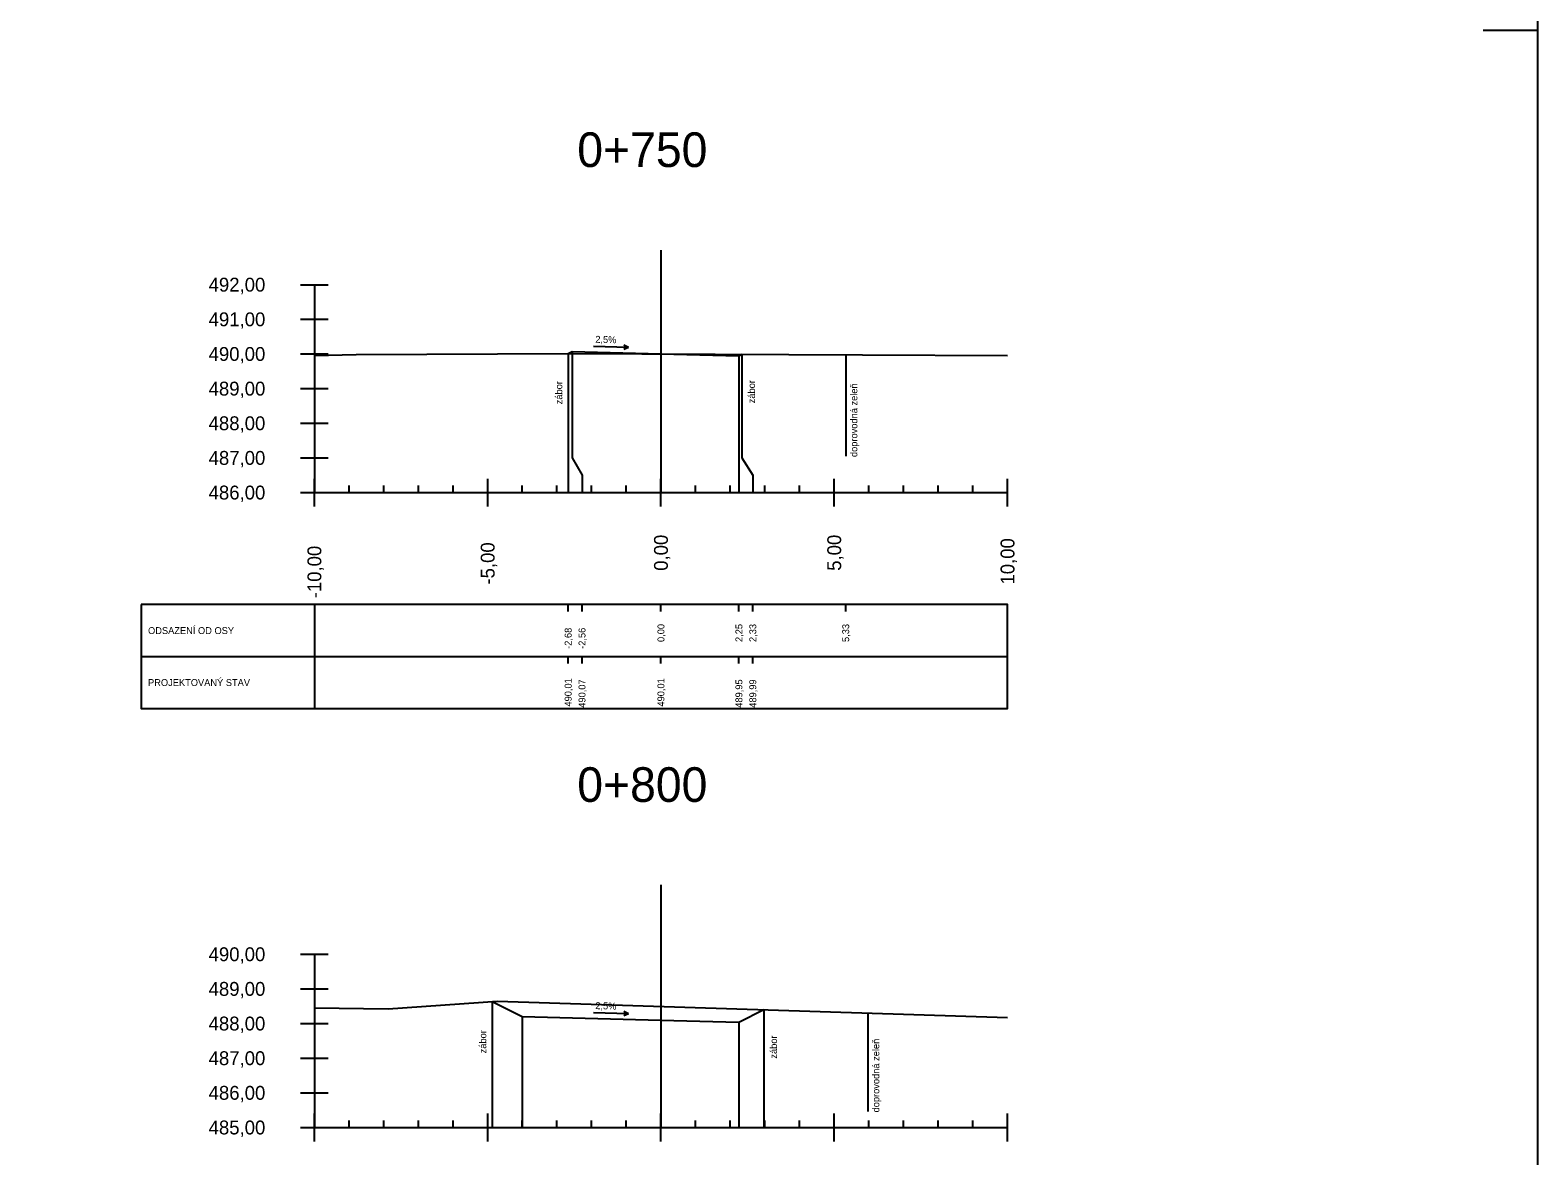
# Model space of a CAD drawing. Extents: x -631407 to -631215, y -1089700 to -1088598.
# Drawn here: x -631346.67 to -631303.16, y -1089673.38 to -1089640.89 of the extents above; entities that cross this region are included whole.
import ezdxf

# ---------------------------------------------------------------- set-up
doc = ezdxf.new("R2010")
doc.units = 0
for name, color, linetype in [('08_LEGENDA_HV', 7, 'Continuous'), ('59', 7, 'Continuous'), ('DTM-Breaklines', 7, 'Continuous'), ('NIVELETA_VYSKY', 7, 'Continuous'), ('REZ_BODY', 7, 'Continuous'), ('REZ_ODSTUPY', 7, 'Continuous'), ('REZ_POPIS', 7, 'Continuous'), ('REZ_RAMY', 7, 'Continuous'), ('REZ_STANICENI', 7, 'Continuous'), ('REZ_SVISLE', 7, 'Continuous'), ('REZ_TENKA', 7, 'Continuous'), ('REZ_TLUSTA', 7, 'Continuous'), ('TABULKA_POPIS', 7, 'Continuous'), ('TEREN', 7, 'Continuous'), ('zábor', 7, 'Continuous')]:
    doc.layers.add(name, color=color, linetype=linetype)

msp = doc.modelspace()

# ---------------------------------------------------------------- linework, layer by layer
at = {"layer": '08_LEGENDA_HV'}
msp.add_lwpolyline([(-631303.164, -1089700.294), (-631303.164, -1089581.494), (-631407.014, -1089581.494), (-631407.014, -1089700.294)], close=True, dxfattribs=at)
at = {"layer": '59'}
for p, q in [((-631338.867, -1089648.24), (-631338.067, -1089648.24)), ((-631338.467, -1089648.24), (-631338.467, -1089654.24)), ((-631338.867, -1089649.24), (-631338.067, -1089649.24)), ((-631338.867, -1089650.24), (-631338.067, -1089650.24)), ((-631338.867, -1089651.24), (-631338.067, -1089651.24)), ((-631338.867, -1089652.24), (-631338.067, -1089652.24)), ((-631338.867, -1089653.24), (-631338.067, -1089653.24)), ((-631338.867, -1089654.24), (-631338.067, -1089654.24)), ((-631338.867, -1089667.565), (-631338.067, -1089667.565)), ((-631338.467, -1089667.565), (-631338.467, -1089672.565)), ((-631338.867, -1089668.565), (-631338.067, -1089668.565)), ((-631338.867, -1089669.565), (-631338.067, -1089669.565)), ((-631338.867, -1089670.565), (-631338.067, -1089670.565)), ((-631338.867, -1089671.565), (-631338.067, -1089671.565)), ((-631338.867, -1089672.565), (-631338.067, -1089672.565))]:
    msp.add_line(p, q, dxfattribs=at)
at = {"layer": 'DTM-Breaklines'}
msp.add_line((-631304.744, -1089640.894), (-631303.164, -1089640.894), dxfattribs=at)
at = {"layer": 'REZ_RAMY'}
for p, q in [((-631343.467, -1089657.474), (-631343.467, -1089660.474)), ((-631338.467, -1089657.474), (-631338.467, -1089660.474)), ((-631331.145, -1089657.674), (-631331.145, -1089657.474)), ((-631330.745, -1089657.674), (-631330.745, -1089657.474)), ((-631328.467, -1089657.674), (-631328.467, -1089657.474)), ((-631326.217, -1089657.674), (-631326.217, -1089657.474)), ((-631325.817, -1089657.674), (-631325.817, -1089657.474)), ((-631323.136, -1089657.674), (-631323.136, -1089657.474)), ((-631343.467, -1089658.974), (-631318.467, -1089658.974)), ((-631331.145, -1089659.174), (-631331.145, -1089658.974)), ((-631330.745, -1089659.174), (-631330.745, -1089658.974)), ((-631328.467, -1089659.174), (-631328.467, -1089658.974)), ((-631326.217, -1089659.174), (-631326.217, -1089658.974)), ((-631325.817, -1089659.174), (-631325.817, -1089658.974))]:
    msp.add_line(p, q, dxfattribs=at)
msp.add_lwpolyline([(-631343.467, -1089657.474), (-631343.467, -1089660.474), (-631318.467, -1089660.474), (-631318.467, -1089657.474)], close=True, dxfattribs=at)
at = {"layer": 'REZ_SVISLE'}
for points in [[(-631331.025, -1089650.169), (-631331.025, -1089653.24), (-631330.745, -1089653.74), (-631330.745, -1089654.24)], [(-631331.145, -1089650.229), (-631331.145, -1089653.24), (-631331.145, -1089653.74), (-631331.145, -1089654.24)], [(-631328.467, -1089650.233), (-631328.467, -1089653.24), (-631328.467, -1089653.74), (-631328.467, -1089654.24)], [(-631326.217, -1089650.289), (-631326.217, -1089653.24), (-631326.217, -1089653.74), (-631326.217, -1089654.24)], [(-631326.136, -1089650.248), (-631326.136, -1089653.24), (-631325.817, -1089653.74), (-631325.817, -1089654.24)], [(-631333.338, -1089668.93), (-631333.338, -1089671.565), (-631333.338, -1089672.065), (-631333.338, -1089672.565)], [(-631325.501, -1089669.163), (-631325.501, -1089671.565), (-631325.501, -1089672.065), (-631325.501, -1089672.565)], [(-631332.467, -1089669.365), (-631332.467, -1089671.565), (-631332.467, -1089672.065), (-631332.467, -1089672.565)], [(-631328.467, -1089669.465), (-631328.467, -1089671.565), (-631328.467, -1089672.065), (-631328.467, -1089672.565)], [(-631326.217, -1089669.521), (-631326.217, -1089671.565), (-631326.217, -1089672.065), (-631326.217, -1089672.565)]]:
    msp.add_lwpolyline(points, dxfattribs=at)
at = {"layer": 'REZ_TENKA'}
for p, q in [((-631337.467, -1089654.24), (-631337.467, -1089654.04)), ((-631336.467, -1089654.24), (-631336.467, -1089654.04)), ((-631335.467, -1089654.24), (-631335.467, -1089654.04)), ((-631334.467, -1089654.24), (-631334.467, -1089654.04)), ((-631332.467, -1089654.24), (-631332.467, -1089654.04)), ((-631331.467, -1089654.24), (-631331.467, -1089654.04)), ((-631330.467, -1089654.24), (-631330.467, -1089654.04)), ((-631329.467, -1089654.24), (-631329.467, -1089654.04)), ((-631327.467, -1089654.24), (-631327.467, -1089654.04)), ((-631326.467, -1089654.24), (-631326.467, -1089654.04)), ((-631325.467, -1089654.24), (-631325.467, -1089654.04)), ((-631324.467, -1089654.24), (-631324.467, -1089654.04)), ((-631322.467, -1089654.24), (-631322.467, -1089654.04)), ((-631321.467, -1089654.24), (-631321.467, -1089654.04)), ((-631320.467, -1089654.24), (-631320.467, -1089654.04)), ((-631319.467, -1089654.24), (-631319.467, -1089654.04)), ((-631337.467, -1089672.565), (-631337.467, -1089672.365)), ((-631336.467, -1089672.565), (-631336.467, -1089672.365)), ((-631335.467, -1089672.565), (-631335.467, -1089672.365)), ((-631334.467, -1089672.565), (-631334.467, -1089672.365)), ((-631332.467, -1089672.565), (-631332.467, -1089672.365)), ((-631331.467, -1089672.565), (-631331.467, -1089672.365)), ((-631330.467, -1089672.565), (-631330.467, -1089672.365)), ((-631329.467, -1089672.565), (-631329.467, -1089672.365)), ((-631327.467, -1089672.565), (-631327.467, -1089672.365)), ((-631326.467, -1089672.565), (-631326.467, -1089672.365)), ((-631325.467, -1089672.565), (-631325.467, -1089672.365)), ((-631324.467, -1089672.565), (-631324.467, -1089672.365)), ((-631322.467, -1089672.565), (-631322.467, -1089672.365)), ((-631321.467, -1089672.565), (-631321.467, -1089672.365)), ((-631320.467, -1089672.565), (-631320.467, -1089672.365)), ((-631319.467, -1089672.565), (-631319.467, -1089672.365))]:
    msp.add_line(p, q, dxfattribs=at)
at = {"layer": 'REZ_TLUSTA'}
for p, q in [((-631328.467, -1089647.24), (-631328.467, -1089654.24)), ((-631338.467, -1089654.64), (-631338.467, -1089653.84)), ((-631333.467, -1089654.64), (-631333.467, -1089653.84)), ((-631328.467, -1089654.64), (-631328.467, -1089653.84)), ((-631323.467, -1089654.64), (-631323.467, -1089653.84)), ((-631318.467, -1089654.64), (-631318.467, -1089653.84)), ((-631338.467, -1089654.24), (-631318.467, -1089654.24)), ((-631328.467, -1089665.565), (-631328.467, -1089672.565)), ((-631338.467, -1089672.965), (-631338.467, -1089672.165)), ((-631333.467, -1089672.965), (-631333.467, -1089672.165)), ((-631328.467, -1089672.965), (-631328.467, -1089672.165)), ((-631323.467, -1089672.965), (-631323.467, -1089672.165)), ((-631318.467, -1089672.965), (-631318.467, -1089672.165)), ((-631338.467, -1089672.565), (-631318.467, -1089672.565))]:
    msp.add_line(p, q, dxfattribs=at)
at = {"layer": 'TEREN'}
for points in [[(-631331.145, -1089650.229), (-631331.025, -1089650.169), (-631328.467, -1089650.233), (-631326.217, -1089650.289), (-631326.136, -1089650.248)], [(-631338.467, -1089650.285), (-631337.266, -1089650.251), (-631331.148, -1089650.229), (-631322.651, -1089650.262), (-631318.467, -1089650.286)], [(-631338.467, -1089669.116), (-631336.335, -1089669.136), (-631333.181, -1089668.919), (-631318.467, -1089669.386)], [(-631333.338, -1089668.93), (-631332.467, -1089669.365), (-631328.467, -1089669.465), (-631326.217, -1089669.521), (-631325.501, -1089669.163)]]:
    msp.add_lwpolyline(points, dxfattribs=at)
at = {"layer": 'zábor'}
for p, q in [((-631329.401, -1089650.053), (-631330.409, -1089650.028)), ((-631329.401, -1089650.053), (-631329.54, -1089650.111)), ((-631329.401, -1089650.053), (-631329.537, -1089649.989)), ((-631323.136, -1089650.26), (-631323.136, -1089653.191)), ((-631329.401, -1089669.285), (-631330.409, -1089669.26)), ((-631329.401, -1089669.285), (-631329.54, -1089669.343)), ((-631329.401, -1089669.285), (-631329.537, -1089669.221)), ((-631322.501, -1089669.258), (-631322.501, -1089672.106))]:
    msp.add_line(p, q, dxfattribs=at)

# ---------------------------------------------------------------- texts
at = {"layer": 'NIVELETA_VYSKY'}
for s, p in [('490,01', (-631331.045, -1089660.417)), ('490,07', (-631330.645, -1089660.45)), ('490,01', (-631328.367, -1089660.417)), ('489,95', (-631326.117, -1089660.45)), ('489,99', (-631325.717, -1089660.45))]:
    msp.add_text(s, height=0.2, rotation=90, dxfattribs=at).set_placement(p)
at = {"layer": 'REZ_BODY'}
for s, p in [('-2,68', (-631331.045, -1089658.751)), ('-2,56', (-631330.645, -1089658.751)), ('0,00', (-631328.367, -1089658.553)), ('2,25', (-631326.117, -1089658.553)), ('2,33', (-631325.717, -1089658.553)), ('5,33', (-631323.036, -1089658.553))]:
    msp.add_text(s, height=0.2, rotation=90, dxfattribs=at).set_placement(p)
at = {"layer": 'REZ_ODSTUPY'}
for s, p in [('-10,00', (-631338.267, -1089657.292)), ('-5,00', (-631333.267, -1089656.895)), ('0,00', (-631328.267, -1089656.498)), ('5,00', (-631323.267, -1089656.498)), ('10,00', (-631318.267, -1089656.895))]:
    msp.add_text(s, height=0.4, rotation=90, dxfattribs=at).set_placement(p)
at = {"layer": 'REZ_POPIS'}
for s, p in [('492,00', (-631341.519, -1089648.44)), ('491,00', (-631341.519, -1089649.44)), ('490,00', (-631341.519, -1089650.44)), ('489,00', (-631341.519, -1089651.44)), ('488,00', (-631341.519, -1089652.44)), ('487,00', (-631341.519, -1089653.44)), ('486,00', (-631341.519, -1089654.44)), ('490,00', (-631341.519, -1089667.765)), ('489,00', (-631341.519, -1089668.765)), ('488,00', (-631341.519, -1089669.765)), ('487,00', (-631341.519, -1089670.765)), ('486,00', (-631341.519, -1089671.765)), ('485,00', (-631341.519, -1089672.765))]:
    msp.add_text(s, height=0.4, dxfattribs=at).set_placement(p)
at = {"layer": 'REZ_STANICENI'}
for s, p in [('0+750', (-631330.882, -1089644.844)), ('0+800', (-631330.882, -1089663.168))]:
    msp.add_text(s, height=1, dxfattribs=at).set_placement(p)
at = {"layer": 'TABULKA_POPIS'}
for s, p in [('ODSAZENÍ OD OSY', (-631343.267, -1089658.324)), ('PROJEKTOVANÝ STAV', (-631343.267, -1089659.824))]:
    msp.add_text(s, height=0.2, dxfattribs=at).set_placement(p)
at = {"layer": 'zábor'}
for s, rotation, p in [('2,5%', 358.5679, (-631330.364, -1089649.916)), ('zábor', 90, (-631331.315, -1089651.692)), ('zábor', 90, (-631325.753, -1089651.663)), ('doprovodná zeleň', 90, (-631322.8, -1089653.215)), ('2,5%', 358.5679, (-631330.364, -1089669.148)), ('zábor', 90, (-631333.508, -1089670.425)), ('zábor', 90, (-631325.118, -1089670.577)), ('doprovodná zeleň', 90, (-631322.166, -1089672.13))]:
    msp.add_text(s, height=0.2, rotation=rotation, dxfattribs=at).set_placement(p)

doc.saveas('drawing.dxf')
